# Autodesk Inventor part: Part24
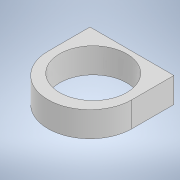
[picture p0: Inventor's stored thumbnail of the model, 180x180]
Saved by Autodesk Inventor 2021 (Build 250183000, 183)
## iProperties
Created: 2021-07
Part Number: Part24
Material: Generic
Document SubType Name: Modeling
Designer: TARUN
Density: 1 g/cm^3
Appearance: Default
Author: TARUN
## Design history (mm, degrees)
sketch "Sketch1"
  geometry: L1 (-7.998, 1.762)-(2.002, 1.762); L2 (2.002, 1.762)-(2.002, -1.238); L3 (2.002, -1.238)-(-7.998, -1.238); L4 (-7.998, -1.238)-(-7.998, 1.762); 1 further point
  constraints: 8 end point, 2 parallel, 1 horizontal, 1 perpendicular
  dimensions: "d0" = 10 distance of L2.end L3.end; "d1" = 3 distance of L1.end L2.end
extrude "Extrusion1" new body sketch "Sketch1" distance "d2" = 10; taper "d3" = 0 deg
sketch "Sketch2"
  geometry: 2 further points
hole "Hole1" sketch "Sketch2" at (4.953, -4.574) diameter "d4" = 8; stored, may be unused: countersink angle "d8" = 90 deg, drill point angle "d10" = 0 deg; dims "d5" = 6, "d6" = 4, "d7" = 2, "d9" = 8
fillet "Fillet1" dims "d11" = 5
body "Solid1"
